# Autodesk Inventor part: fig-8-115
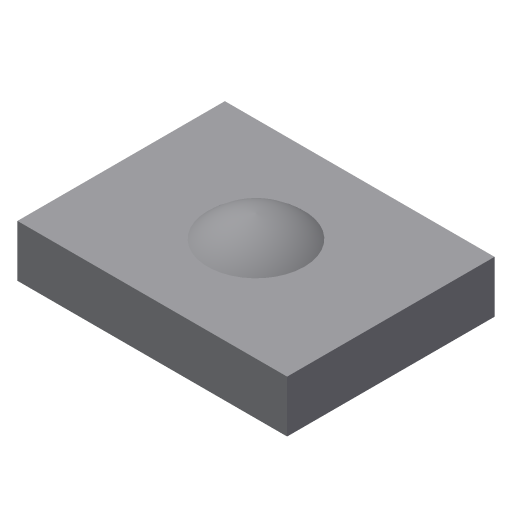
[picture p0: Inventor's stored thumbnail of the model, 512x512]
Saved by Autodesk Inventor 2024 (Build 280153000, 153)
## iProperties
Created: 2009-09
Part Number: fig-8-115
Document SubType Name: Modeling
Designer: Sham
Density: 1 g/cm^3
Material: Generic
Appearance: Default
Author: Sham
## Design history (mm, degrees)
sketch "Sketch1"
  geometry: L1 (-26, 20)-(0, 20); L2 (0, 20)-(0, 0); L3 (0, 0)-(-26, 0); L4 (-26, 0)-(-26, 20)
  constraints: 8 end point, 2 parallel, 1 horizontal, 1 perpendicular
extrude "Extrusion1" new body sketch "Sketch1" distance "d0" = 5; taper "d1" = 0 deg
workplane "Work Plane1"
feature "Sculpt2"
body "Solid1"
sketch "Sketch2"
  geometry: L1 (13, 8)-(13, 5); A1 r 7.517 centre (12.377, -0.349) between (17.658, 5) and (13, 7.142)
  constraints: 2 end point, 2 point on circle, 1 centre point
body "Srf2"
feature "RevolutionSrf2" dims angle "d4" = 90 deg
